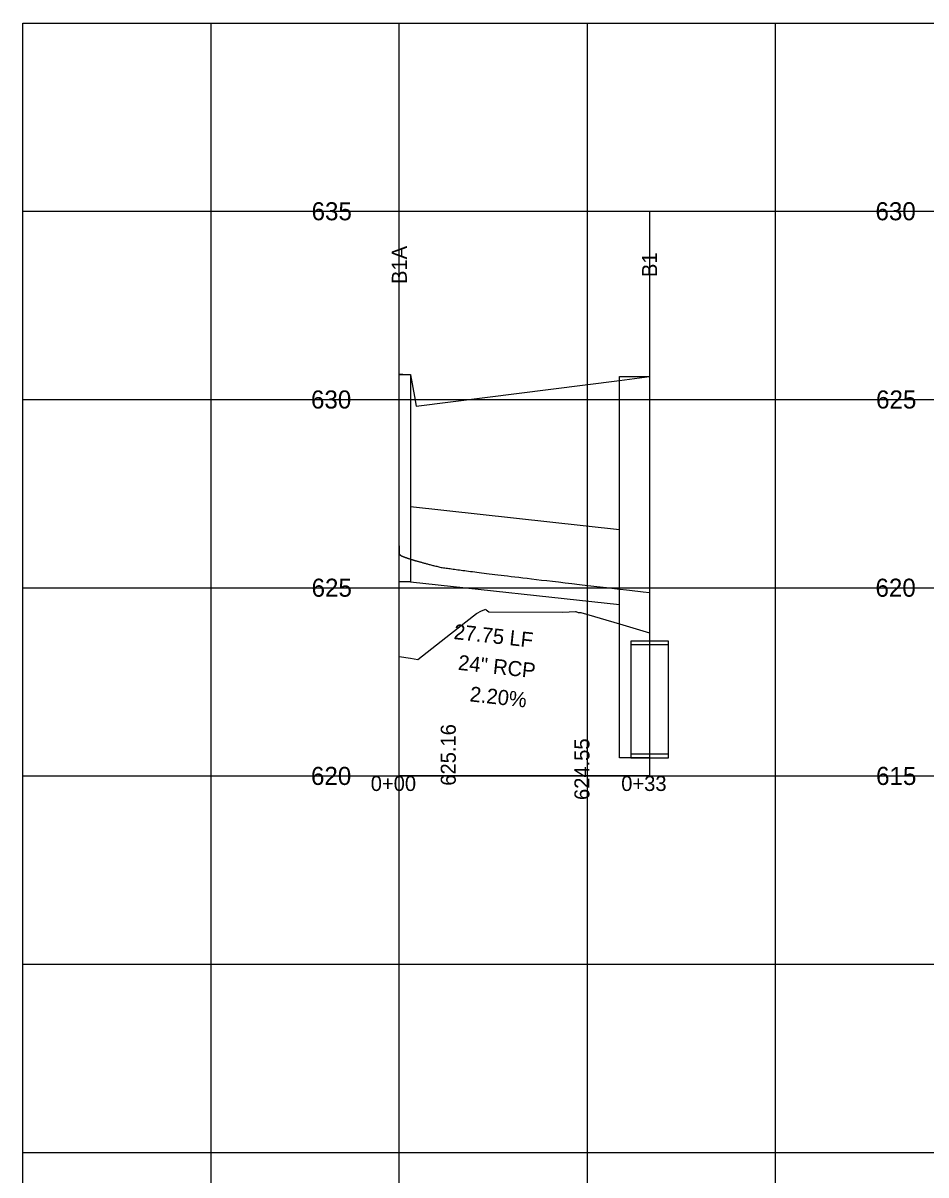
# Model space of a CAD drawing. Extents: x 2254979 to 2278074, y 13790855 to 13792793.
# Drawn here: x 2276749.4 to 2276869.4, y 13792639.6 to 13792792.6 of the extents above; entities that cross this region are included whole.
import ezdxf

# ---------------------------------------------------------------- set-up
doc = ezdxf.new("R2010")
doc.units = 0
for name, color, linetype in [('blank4', 7, 'Continuous'), ('BORD_grid_bottom_major_5int', 7, 'Continuous'), ('D_DRN_PROF_HGL', 7, 'Continuous'), ('D_PROF_1', 7, 'Continuous'), ('D_PROF_NOTES_1', 7, 'Continuous'), ('Default', 7, 'Continuous'), ('Drain_PipeInside', 7, 'Continuous'), ('E_Terrain', 7, 'Continuous'), ('Inlet', 7, 'Continuous'), ('z - Construction', 7, 'Continuous')]:
    doc.layers.add(name, color=color, linetype=linetype)

msp = doc.modelspace()

# ---------------------------------------------------------------- linework, layer by layer
at = {"layer": 'blank4'}
msp.add_lwpolyline([(2276799.4, 13792692.6), (2276799.4, 13792767.6), (2276832.65, 13792767.6), (2276832.65, 13792692.6)], close=True, dxfattribs=at)
at = {"layer": 'BORD_grid_bottom_major_5int'}
for p, q in [((2276749.4, 13792792.6), (2277074.4, 13792792.6)), ((2276749.4, 13792492.6), (2276749.4, 13792792.6)), ((2276774.4, 13792492.6), (2276774.4, 13792792.6)), ((2276799.4, 13792492.6), (2276799.4, 13792792.6)), ((2276824.4, 13792492.6), (2276824.4, 13792792.6)), ((2276849.4, 13792492.6), (2276849.4, 13792792.6)), ((2276749.4, 13792767.6), (2277074.4, 13792767.6)), ((2276749.4, 13792742.6), (2277074.4, 13792742.6)), ((2276749.4, 13792717.6), (2277074.4, 13792717.6)), ((2276749.4, 13792692.6), (2277074.4, 13792692.6)), ((2276749.4, 13792667.6), (2277074.4, 13792667.6)), ((2276749.4, 13792642.6), (2277074.4, 13792642.6))]:
    msp.add_line(p, q, dxfattribs=at)
at = {"layer": 'D_DRN_PROF_HGL'}
msp.add_lwpolyline([(2276799.4, 13792723.14), (2276799.4, 13792722.06), (2276799.4, 13792722.06), (2276799.41, 13792722.05), (2276799.41, 13792722.05), (2276799.41, 13792722.04), (2276799.41, 13792722.04), (2276799.41, 13792722.03), (2276799.42, 13792722.02), (2276799.42, 13792722.02), (2276799.42, 13792722.01), (2276799.43, 13792722.01), (2276799.43, 13792722), (2276799.44, 13792721.99), (2276799.45, 13792721.99), (2276799.45, 13792721.98), (2276799.46, 13792721.98), (2276799.47, 13792721.97), (2276799.48, 13792721.96), (2276799.48, 13792721.95), (2276799.49, 13792721.95), (2276799.5, 13792721.94), (2276799.51, 13792721.93), (2276799.53, 13792721.93), (2276799.54, 13792721.92), (2276799.55, 13792721.91), (2276799.56, 13792721.9), (2276799.58, 13792721.89), (2276799.59, 13792721.89), (2276799.61, 13792721.88), (2276799.62, 13792721.87), (2276799.64, 13792721.86), (2276799.65, 13792721.85), (2276799.67, 13792721.84), (2276799.69, 13792721.83), (2276799.71, 13792721.83), (2276799.73, 13792721.82), (2276799.75, 13792721.81), (2276799.77, 13792721.8), (2276799.79, 13792721.79), (2276799.82, 13792721.78), (2276799.84, 13792721.77), (2276799.86, 13792721.76), (2276799.89, 13792721.75), (2276799.91, 13792721.74), (2276799.94, 13792721.72), (2276799.97, 13792721.71), (2276800, 13792721.7), (2276800.03, 13792721.69), (2276800.06, 13792721.68), (2276800.09, 13792721.67), (2276800.12, 13792721.65), (2276800.15, 13792721.64), (2276800.19, 13792721.63), (2276800.22, 13792721.62), (2276800.26, 13792721.6), (2276800.3, 13792721.59), (2276800.34, 13792721.58), (2276800.37, 13792721.56), (2276800.42, 13792721.55), (2276800.46, 13792721.54), (2276800.5, 13792721.52), (2276800.54, 13792721.51), (2276800.59, 13792721.49), (2276800.63, 13792721.48), (2276800.68, 13792721.46), (2276800.73, 13792721.45), (2276800.78, 13792721.43), (2276800.83, 13792721.41), (2276800.88, 13792721.4), (2276800.94, 13792721.38), (2276800.99, 13792721.36), (2276801.05, 13792721.35), (2276801.11, 13792721.33), (2276801.17, 13792721.31), (2276801.23, 13792721.29), (2276801.29, 13792721.27), (2276801.35, 13792721.25), (2276801.42, 13792721.23), (2276801.49, 13792721.21), (2276801.56, 13792721.19), (2276801.63, 13792721.17), (2276801.7, 13792721.15), (2276801.77, 13792721.13), (2276801.85, 13792721.11), (2276801.93, 13792721.09), (2276802.01, 13792721.06), (2276802.09, 13792721.04), (2276802.17, 13792721.02), (2276802.26, 13792720.99), (2276802.35, 13792720.97), (2276802.44, 13792720.95), (2276802.53, 13792720.92), (2276802.62, 13792720.89), (2276802.72, 13792720.87), (2276802.82, 13792720.84), (2276802.92, 13792720.81), (2276803.03, 13792720.79), (2276803.13, 13792720.76), (2276803.24, 13792720.73), (2276803.36, 13792720.7), (2276803.47, 13792720.67), (2276803.59, 13792720.64), (2276803.71, 13792720.6), (2276803.84, 13792720.57), (2276803.96, 13792720.54), (2276804.09, 13792720.51), (2276804.23, 13792720.47), (2276804.37, 13792720.44), (2276804.51, 13792720.4), (2276804.65, 13792720.36), (2276804.8, 13792720.32), (2276804.95, 13792720.29), (2276805.11, 13792720.27), (2276805.27, 13792720.25), (2276805.44, 13792720.22), (2276805.61, 13792720.2), (2276805.79, 13792720.18), (2276805.97, 13792720.15), (2276806.15, 13792720.13), (2276806.34, 13792720.1), (2276806.54, 13792720.07), (2276806.74, 13792720.05), (2276806.95, 13792720.02), (2276807.16, 13792719.99), (2276807.38, 13792719.96), (2276807.61, 13792719.93), (2276807.84, 13792719.9), (2276808.09, 13792719.87), (2276808.34, 13792719.83), (2276808.59, 13792719.8), (2276808.86, 13792719.77), (2276809.13, 13792719.73), (2276809.42, 13792719.7), (2276809.71, 13792719.66), (2276810.02, 13792719.62), (2276810.33, 13792719.58), (2276810.66, 13792719.54), (2276811, 13792719.5), (2276811.35, 13792719.45), (2276811.72, 13792719.41), (2276812.1, 13792719.36), (2276812.49, 13792719.31), (2276812.91, 13792719.26), (2276813.34, 13792719.21), (2276813.79, 13792719.16), (2276814.26, 13792719.1), (2276814.75, 13792719.04), (2276815.26, 13792718.98), (2276815.81, 13792718.91), (2276816.38, 13792718.85), (2276816.98, 13792718.77), (2276817.61, 13792718.7), (2276818.28, 13792718.62), (2276818.99, 13792718.54), (2276819.75, 13792718.45), (2276820.55, 13792718.36), (2276821.42, 13792718.26), (2276822.34, 13792718.15), (2276823.35, 13792718.03), (2276824.43, 13792717.91), (2276825.62, 13792717.77), (2276826.92, 13792717.63), (2276828.36, 13792717.46), (2276829.98, 13792717.28), (2276831.81, 13792717.07), (2276832.65, 13792716.97)], dxfattribs=at)
at = {"layer": 'D_PROF_1'}
msp.add_lwpolyline([(2276799.4, 13792746.02), (2276800.9, 13792745.87), (2276800.9, 13792745.87), (2276800.9, 13792745.87), (2276801.43, 13792742.98), (2276801.65, 13792741.7), (2276828.65, 13792745.13), (2276828.65, 13792745.13), (2276832.65, 13792745.64), (2276832.65, 13792745.64)], dxfattribs=at)
at = {"layer": 'Drain_PipeInside'}
for p, q in [((2276800.9, 13792728.4), (2276828.65, 13792725.35)), ((2276800.9, 13792718.4), (2276828.65, 13792715.35))]:
    msp.add_line(p, q, dxfattribs=at)
for points in [[(2276830.15, 13792695.52), (2276835.15, 13792695.52), (2276835.15, 13792710.52), (2276830.15, 13792710.52)], [(2276830.15, 13792695), (2276835.15, 13792695), (2276835.15, 13792710), (2276830.15, 13792710)]]:
    msp.add_lwpolyline(points, close=True, dxfattribs=at)
at = {"layer": 'E_Terrain'}
msp.add_lwpolyline([(2276799.4, 13792708.46), (2276800.9, 13792708.22), (2276800.9, 13792708.22), (2276801.86, 13792708.07), (2276806.19, 13792711.47), (2276809.67, 13792714.18), (2276810.31, 13792714.51), (2276810.89, 13792714.75), (2276810.94, 13792714.67), (2276811.28, 13792714.41), (2276821.13, 13792714.36), (2276822.81, 13792714.43), (2276822.87, 13792714.42), (2276823.15, 13792714.29), (2276823.47, 13792714.3), (2276823.51, 13792714.3), (2276828.65, 13792712.79), (2276828.65, 13792712.79), (2276832.65, 13792711.62)], dxfattribs=at)
at = {"layer": 'Inlet'}
for points in [[(2276799.4, 13792745.9), (2276800.9, 13792745.9), (2276800.9, 13792718.4), (2276799.4, 13792718.4)], [(2276828.65, 13792745.64), (2276832.65, 13792745.64), (2276832.65, 13792695), (2276828.65, 13792695)]]:
    msp.add_lwpolyline(points, close=True, dxfattribs=at)
at = {"layer": 'z - Construction'}
for p, q in [((2276799.4, 13792742.6), (2276832.65, 13792742.6)), ((2276799.4, 13792717.6), (2276832.65, 13792717.6))]:
    msp.add_line(p, q, dxfattribs=at)

# ---------------------------------------------------------------- texts
at = {"layer": 'D_PROF_NOTES_1'}
for s, rotation, p in [('B1A', 90, (2276800.4, 13792757.94)), ('B1', 90, (2276833.65, 13792758.86)), ('27.75 LF', 353.7227, (2276806.56, 13792710.79)), ('24" RCP', 353.7227, (2276807.13, 13792706.7)), ('2.20%', 353.7227, (2276808.68, 13792702.51)), ('625.16', 90, (2276806.9, 13792691.3)), ('624.55', 90, (2276824.66, 13792689.4))]:
    msp.add_text(s, height=2, rotation=rotation, dxfattribs=at).set_placement(p)
at = {"layer": 'Default'}
for s, height, p in [('635', 2.4, (2276787.74, 13792766.4)), ('630', 2.4, (2276862.66, 13792766.4)), ('630', 2.4, (2276787.66, 13792741.4)), ('625', 2.4, (2276862.74, 13792741.4)), ('625', 2.4, (2276787.74, 13792716.4)), ('620', 2.4, (2276862.66, 13792716.4)), ('620', 2.4, (2276787.66, 13792691.4)), ('615', 2.4, (2276862.74, 13792691.4)), ('0+00', 2, (2276795.6, 13792690.6)), ('0+33', 2, (2276828.88, 13792690.6))]:
    msp.add_text(s, height=height, dxfattribs=at).set_placement(p)

doc.saveas('drawing.dxf')
